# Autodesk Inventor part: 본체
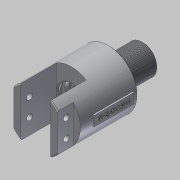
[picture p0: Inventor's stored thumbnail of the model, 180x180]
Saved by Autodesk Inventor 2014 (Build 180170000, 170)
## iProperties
Created: 2019-02
Part Number: 본체
Material: 알루미늄 6061
Document SubType Name: Modeling
Designer: 602-10
Density: 2.71 g/cm^3
Appearance: 알루미늄 - 평지
Author: 602-10
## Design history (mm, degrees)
sketch "스케치1"
  geometry: C1 r 29 at (0, 0); 1 further point
  constraints: 1 centre point, 1 coincident
  dimensions: "d0" = 58 diameter of C1
extrude "돌출1" new body sketch "스케치1" distance "d1" = 74; taper "d2" = 0 deg
sketch "스케치2"
  geometry: L1 (15, 74)-(-15, 74); L2 (-15, 74)-(-15, 38); L3 (-15, 38)-(15, 38); L4 (15, 38)-(15, 74); L5 (29, 74)-(-29, 74) reference; 2 further points
  constraints: 8 end point, 2 midpoint, 2 parallel, 1 horizontal, 1 perpendicular
  dimensions: "d3" = 30 distance of L1.start L1.end; "d4" = 36 distance of L3.end L1.start
extrude "돌출2" cut sketch "스케치2" stored distance "d5" = 10; taper "d6" = 0 deg
sketch "스케치3"
  geometry: L1 (-22, 74)-(22, 74); L2 (29, 74)-(15, 74) reference; L3 (22, 74)-(22, 58); L4 (22, 58)-(35.26, 58); L5 (35.26, 58)-(35.26, 83.924); L6 (35.26, 83.924)-(-35.662, 83.924); L7 (-22, 74)-(-22, 58); L8 (-22, 58)-(-37.539, 58); L9 (-37.539, 58)-(-38.343, 84.862); L10 (-38.343, 84.862)-(-35.662, 83.924); 2 further points
  constraints: 18 end point, 4 perpendicular, 2 parallel, 1 horizontal, 1 horizontal alignment, 1 midpoint, 1 vertical alignment
  dimensions: "d7" = 44 distance of L1.start L1.end; "d8" = 16 distance of L1.end L3.end; "d9" = 16 distance of L1.start L7.end
extrude "돌출3" cut sketch "스케치3" stored distance "d10" = 0; taper "d11" = 0 deg
sketch "스케치4"
  geometry: L1 (-29, 38)-(29, 38) reference; L2 (29, 38)-(29, 0) reference; L3 (29, 0)-(-29, 0) reference; L4 (-29, 0)-(-29, 38) reference; L5 (0, 0)-(0, 38); L6 (-24.819, 38)-(24.819, 38) reference; L7 (14, 38)-(14, 35.35); L8 (14, 35.35)-(17, 35.35); L9 (17, 35.35)-(17, 30.65); L10 (14, 30.65)-(14, 26.35); L11 (14, 26.35)-(17, 26.35); L12 (17, 26.35)-(17, 21.65); L13 (17, 21.65)-(14, 21.65); L14 (14, 21.65)-(14, 18); L15 (14, 18)-(16, 18); L16 (16, 18)-(16, 11); L17 (16, 11)-(4, 11); L18 (4, 11)-(4, 0); L19 (14, 30.65)-(17, 30.65); L20 (0, 0)-(4, 0); L21 (14, 38)-(0, 38); 2 further points
  constraints: 32 end point, 10 parallel, 4 perpendicular, 3 midpoint, 2 collinear, 2 point on line
  dimensions: "d12" = 34 diameter of L9 L5; "d13" = 34 diameter of L12 L5; "d14" = 32 diameter of L16 L5; "d15" = 28 diameter of L14 L5; "d16" = 28 diameter of L10 L5; "d17" = 28 diameter of L7 L5; "d18" = 5 distance from line of L1 point (17, 33); "d19" = 4.7 distance of L8.end L9.end; "d20" = 9 distance of point (17, 33) point (17, 24); "d21" = 4.7 distance of L11.end L12.end; "d22" = 7 distance of L15.end L16.end; "d23" = 27 distance between parallel lines of L1 L17; "d24" = 20 distance between parallel lines of L6 L15 (derived); "d25" = 8 diameter of L18 L5
revolve "회전1" sketch "스케치4" stored, may be unused: angle "d26" = 90 deg
sketch "스케치5"
  geometry: C1 r 13 at (0, 0); 1 further point
  constraints: 1 centre point, 1 coincident
  dimensions: "d27" = 26 diameter of C1
extrude "돌출4" join sketch "스케치5" distance "d28" = 5; taper "d29" = 0 deg
sketch "스케치6"
  geometry: C1 r 15 at (0, 0); 1 further point
  constraints: 1 centre point, 1 coincident
  dimensions: "d30" = 30 diameter of C1
extrude "돌출5" join sketch "스케치6" distance "d31" = 29; taper "d32" = 0 deg
hole "구멍1" diameter "d35" = 12.376; stored, may be unused: countersink angle "d39" = 90 deg, drill point angle "d41" = 118 deg; dims "d33" = 10, "d34" = 10, "d36" = 18, "d37" = 4, "d38" = 2, "d40" = 22
sketch "스케치7"
  geometry: C1 r 4 at (0, 0) reference; 1 further point
extrude "돌출6" cut sketch "스케치7" distance "d42" = 34; taper "d43" = 0 deg
chamfer "모따기1" distance "d44" = 1; stored, may be unused: second distance "d45" = 2, angle "d46" = 45 deg
feature "스레드1" dims "d47" = 10, "d48" = 0
chamfer "모따기2" distance "d49" = 1; stored, may be unused: second distance "d50" = 2, angle "d51" = 45 deg
fillet "모깎기1" dims "d52" = 0.8
sketch "스케치8"
  geometry: L1 (-16, 42.538)-(-16, -4.749) reference; 3 further points
  constraints: 1 vertical alignment
  dimensions: "d53" = 9 vertical distance of point (58, 18.894) point (-7, 9.894); "d54" = 9 distance from line of L1 point (-7, 9.894); "d55" = 18 distance of point (-7, 9.894) point (-7, 27.894)
hole "구멍2" sketch "스케치8" at (-7, 27.894), (-7, 9.894) diameter "d56" = 6; stored, may be unused: countersink angle "d60" = 90 deg, drill point angle "d62" = 118 deg; dims "d57" = 18, "d58" = 4, "d59" = 2, "d61" = 22
node "작업 평면1"
sketch "스케치9"
  geometry: L1 (-5, 5)-(5, 5); L2 (5, 5)-(5, 45); L3 (5, 45)-(-5, 45); L4 (-5, 45)-(-5, 5); L5 (28, 0)-(-28, 0) reference; 2 further points
  constraints: 8 end point, 2 parallel, 1 horizontal, 1 midpoint, 1 perpendicular, 1 vertical alignment
  dimensions: "d64" = 40 distance of L1.end L2.end; "d65" = 10 distance of L2.end L3.end; "d66" = 5 distance between parallel lines of L5 L1
extrude "돌출7" join sketch "스케치9" stored distance "d67" = 34; taper "d68" = 0 deg
sketch "스케치10"
  geometry: L1 (-5, -5)-(-5, 5) reference; 2 further points
  constraints: 1 horizontal alignment, 1 other
  dimensions: "d69" = 20 distance from line of L1 point (-25, 0)
feature "엠보싱1" sketch "스케치10" dims "d70" = 0.5, "d71" = 0
node "솔리드1"
node "절단 모서리 투영1"
